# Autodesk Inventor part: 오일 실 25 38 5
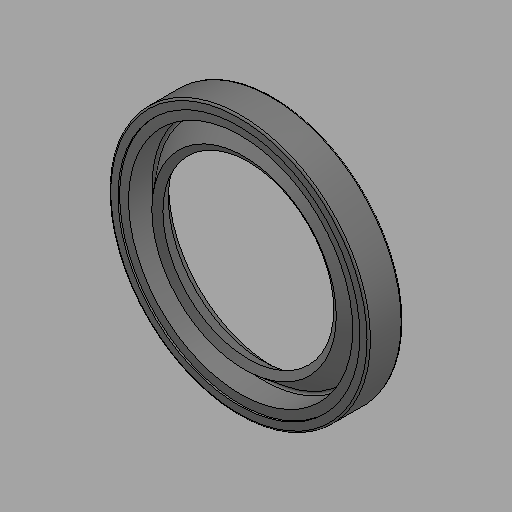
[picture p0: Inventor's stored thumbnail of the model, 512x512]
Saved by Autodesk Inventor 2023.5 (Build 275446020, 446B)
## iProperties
Created: 2025-07
Part Number: 오일 실 25 38 5
Material: 고무
Description: 오일 실 - 비스프링, 조립 GA
Document SubType Name: Modeling
Designer: 1강의실14
Density: 0.93 g/cm^3
Appearance: 기본값
Author: jhkim
Sending System: Autodesk Inventor 2026
Preprocessor: ST-DEVELOPER v20.1
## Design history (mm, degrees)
feature "Solid1"
node "솔리드1"
